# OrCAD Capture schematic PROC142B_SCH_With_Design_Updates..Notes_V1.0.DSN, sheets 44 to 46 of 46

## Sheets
44 44. OSCILLATOR: size C; title: SOC RESETs AND IOs, AND EXTERNAL LVCMOS CLOCK (OSCILLATOR)
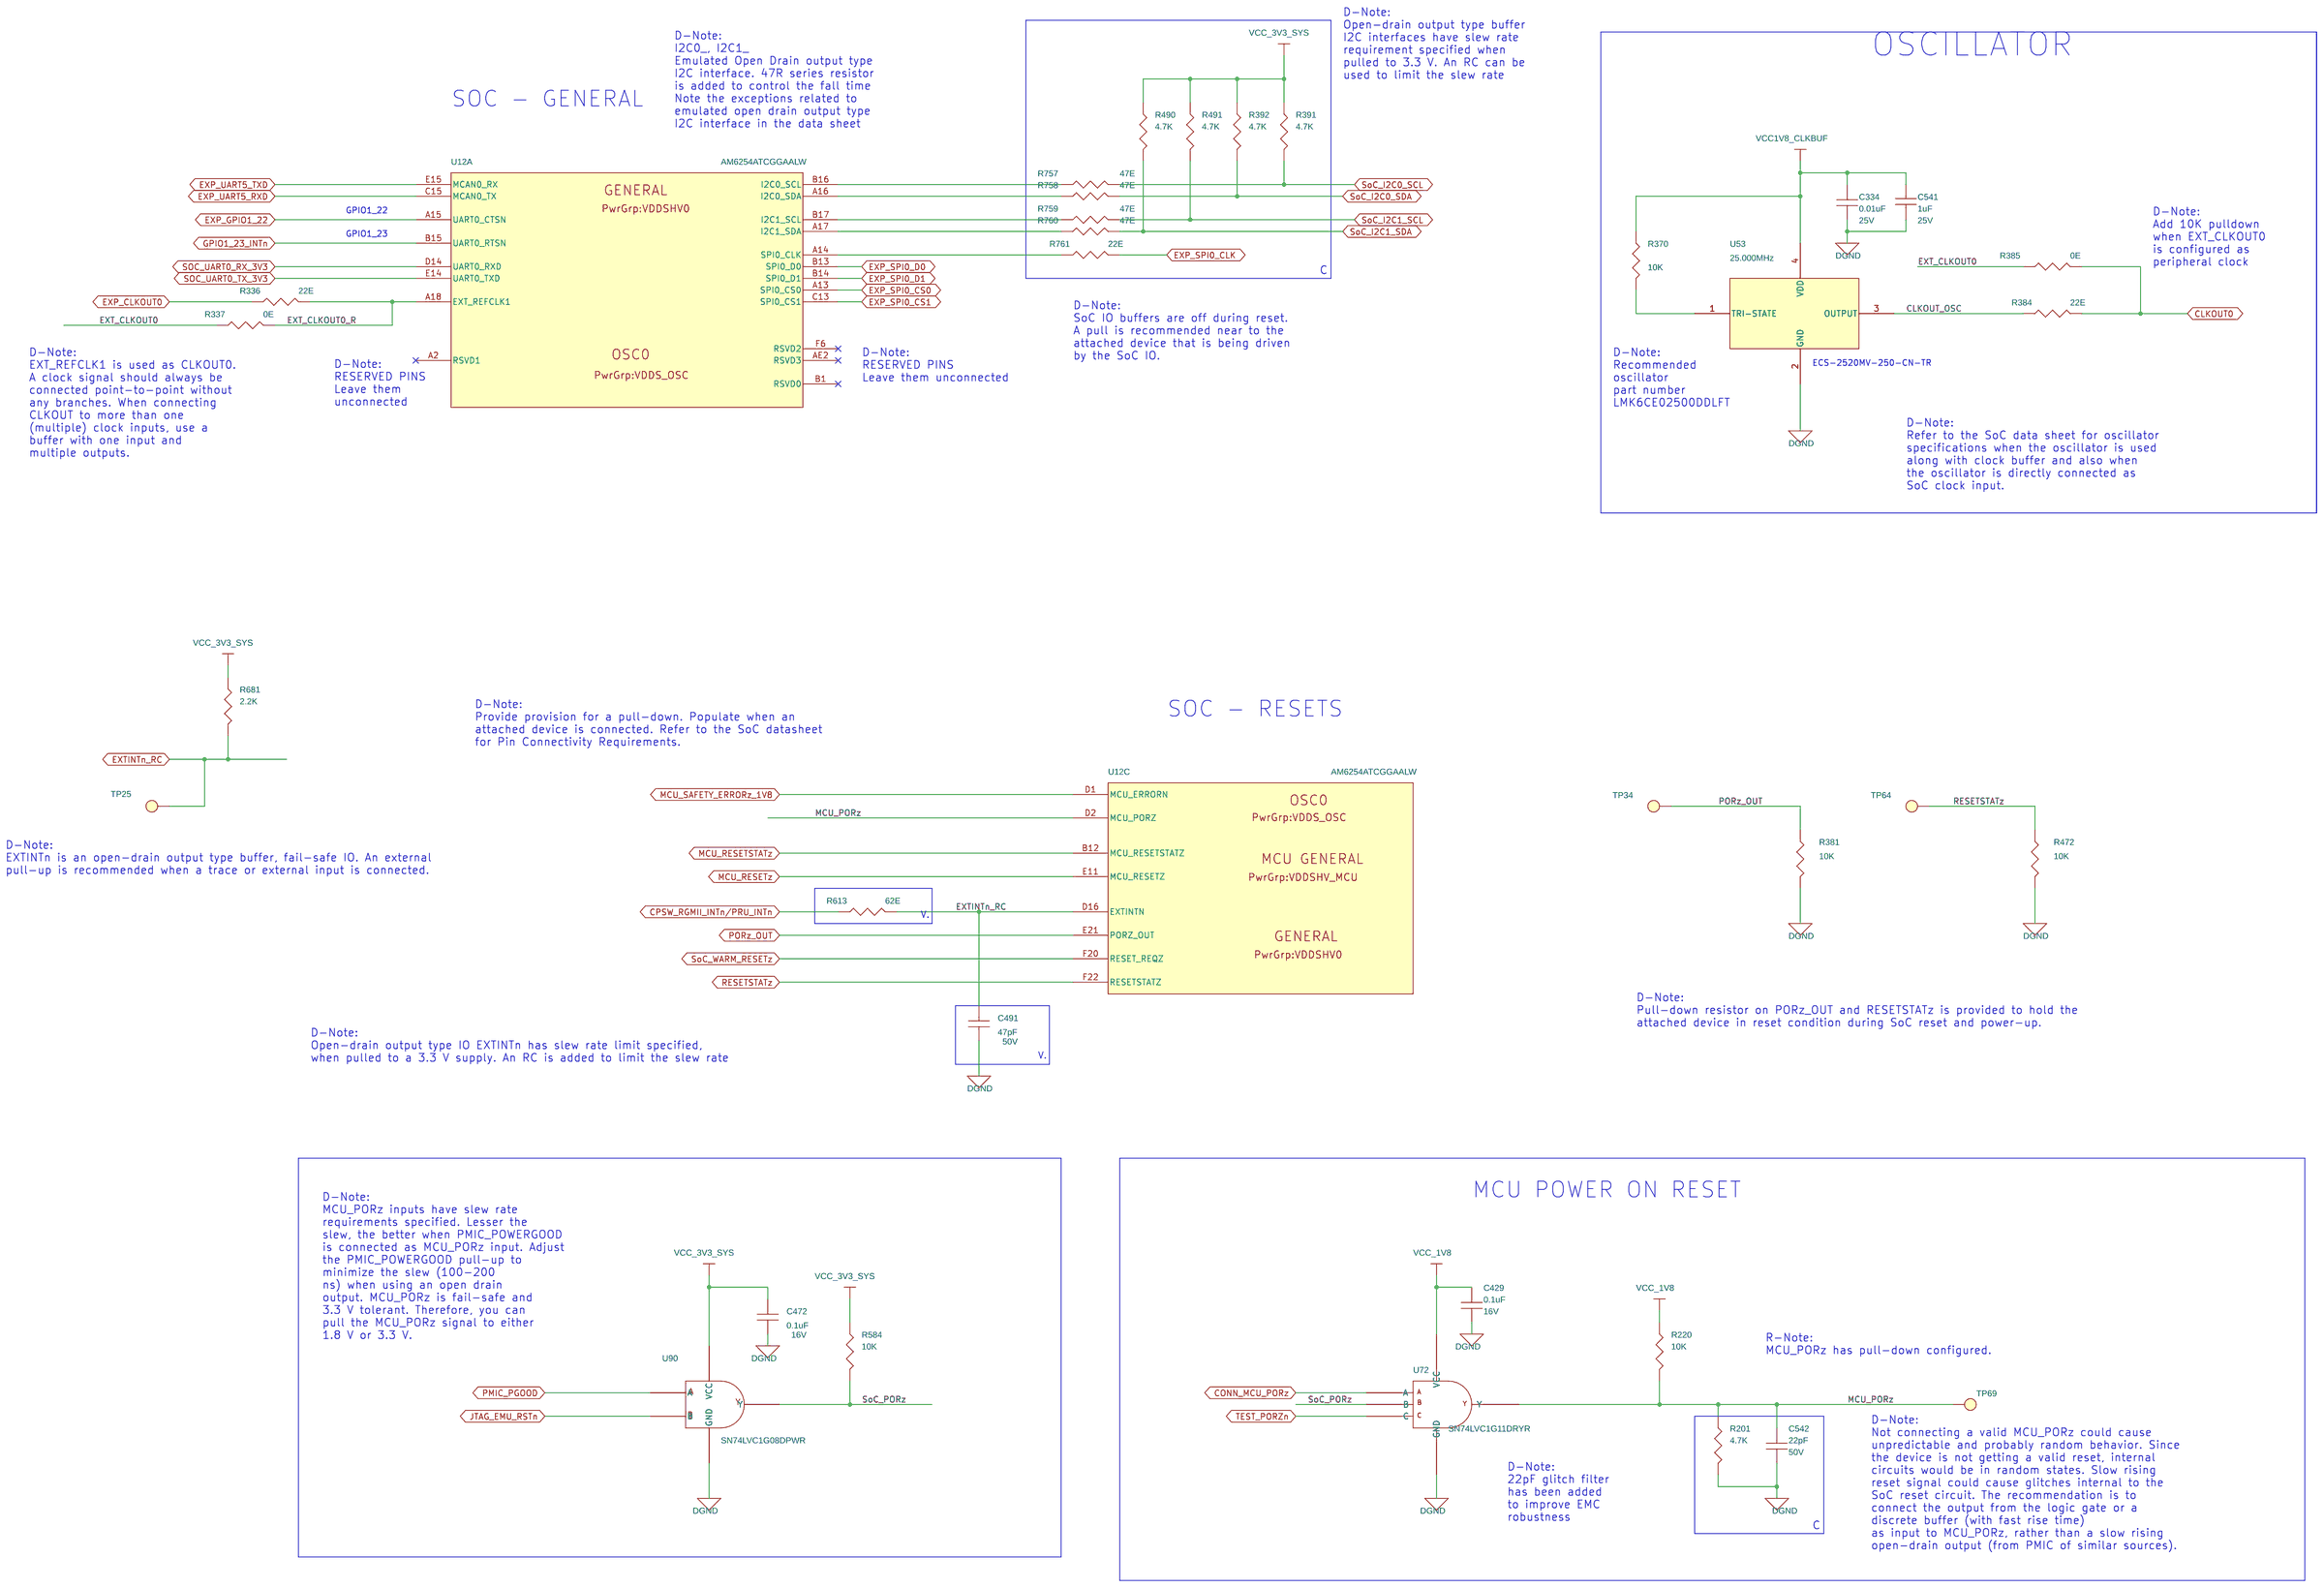
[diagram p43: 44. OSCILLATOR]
45 45. RESET: size C; title: SOC PUSH BUTTON RESET INPUTS, DEBOUNCE LOGIC FOR RC RESET
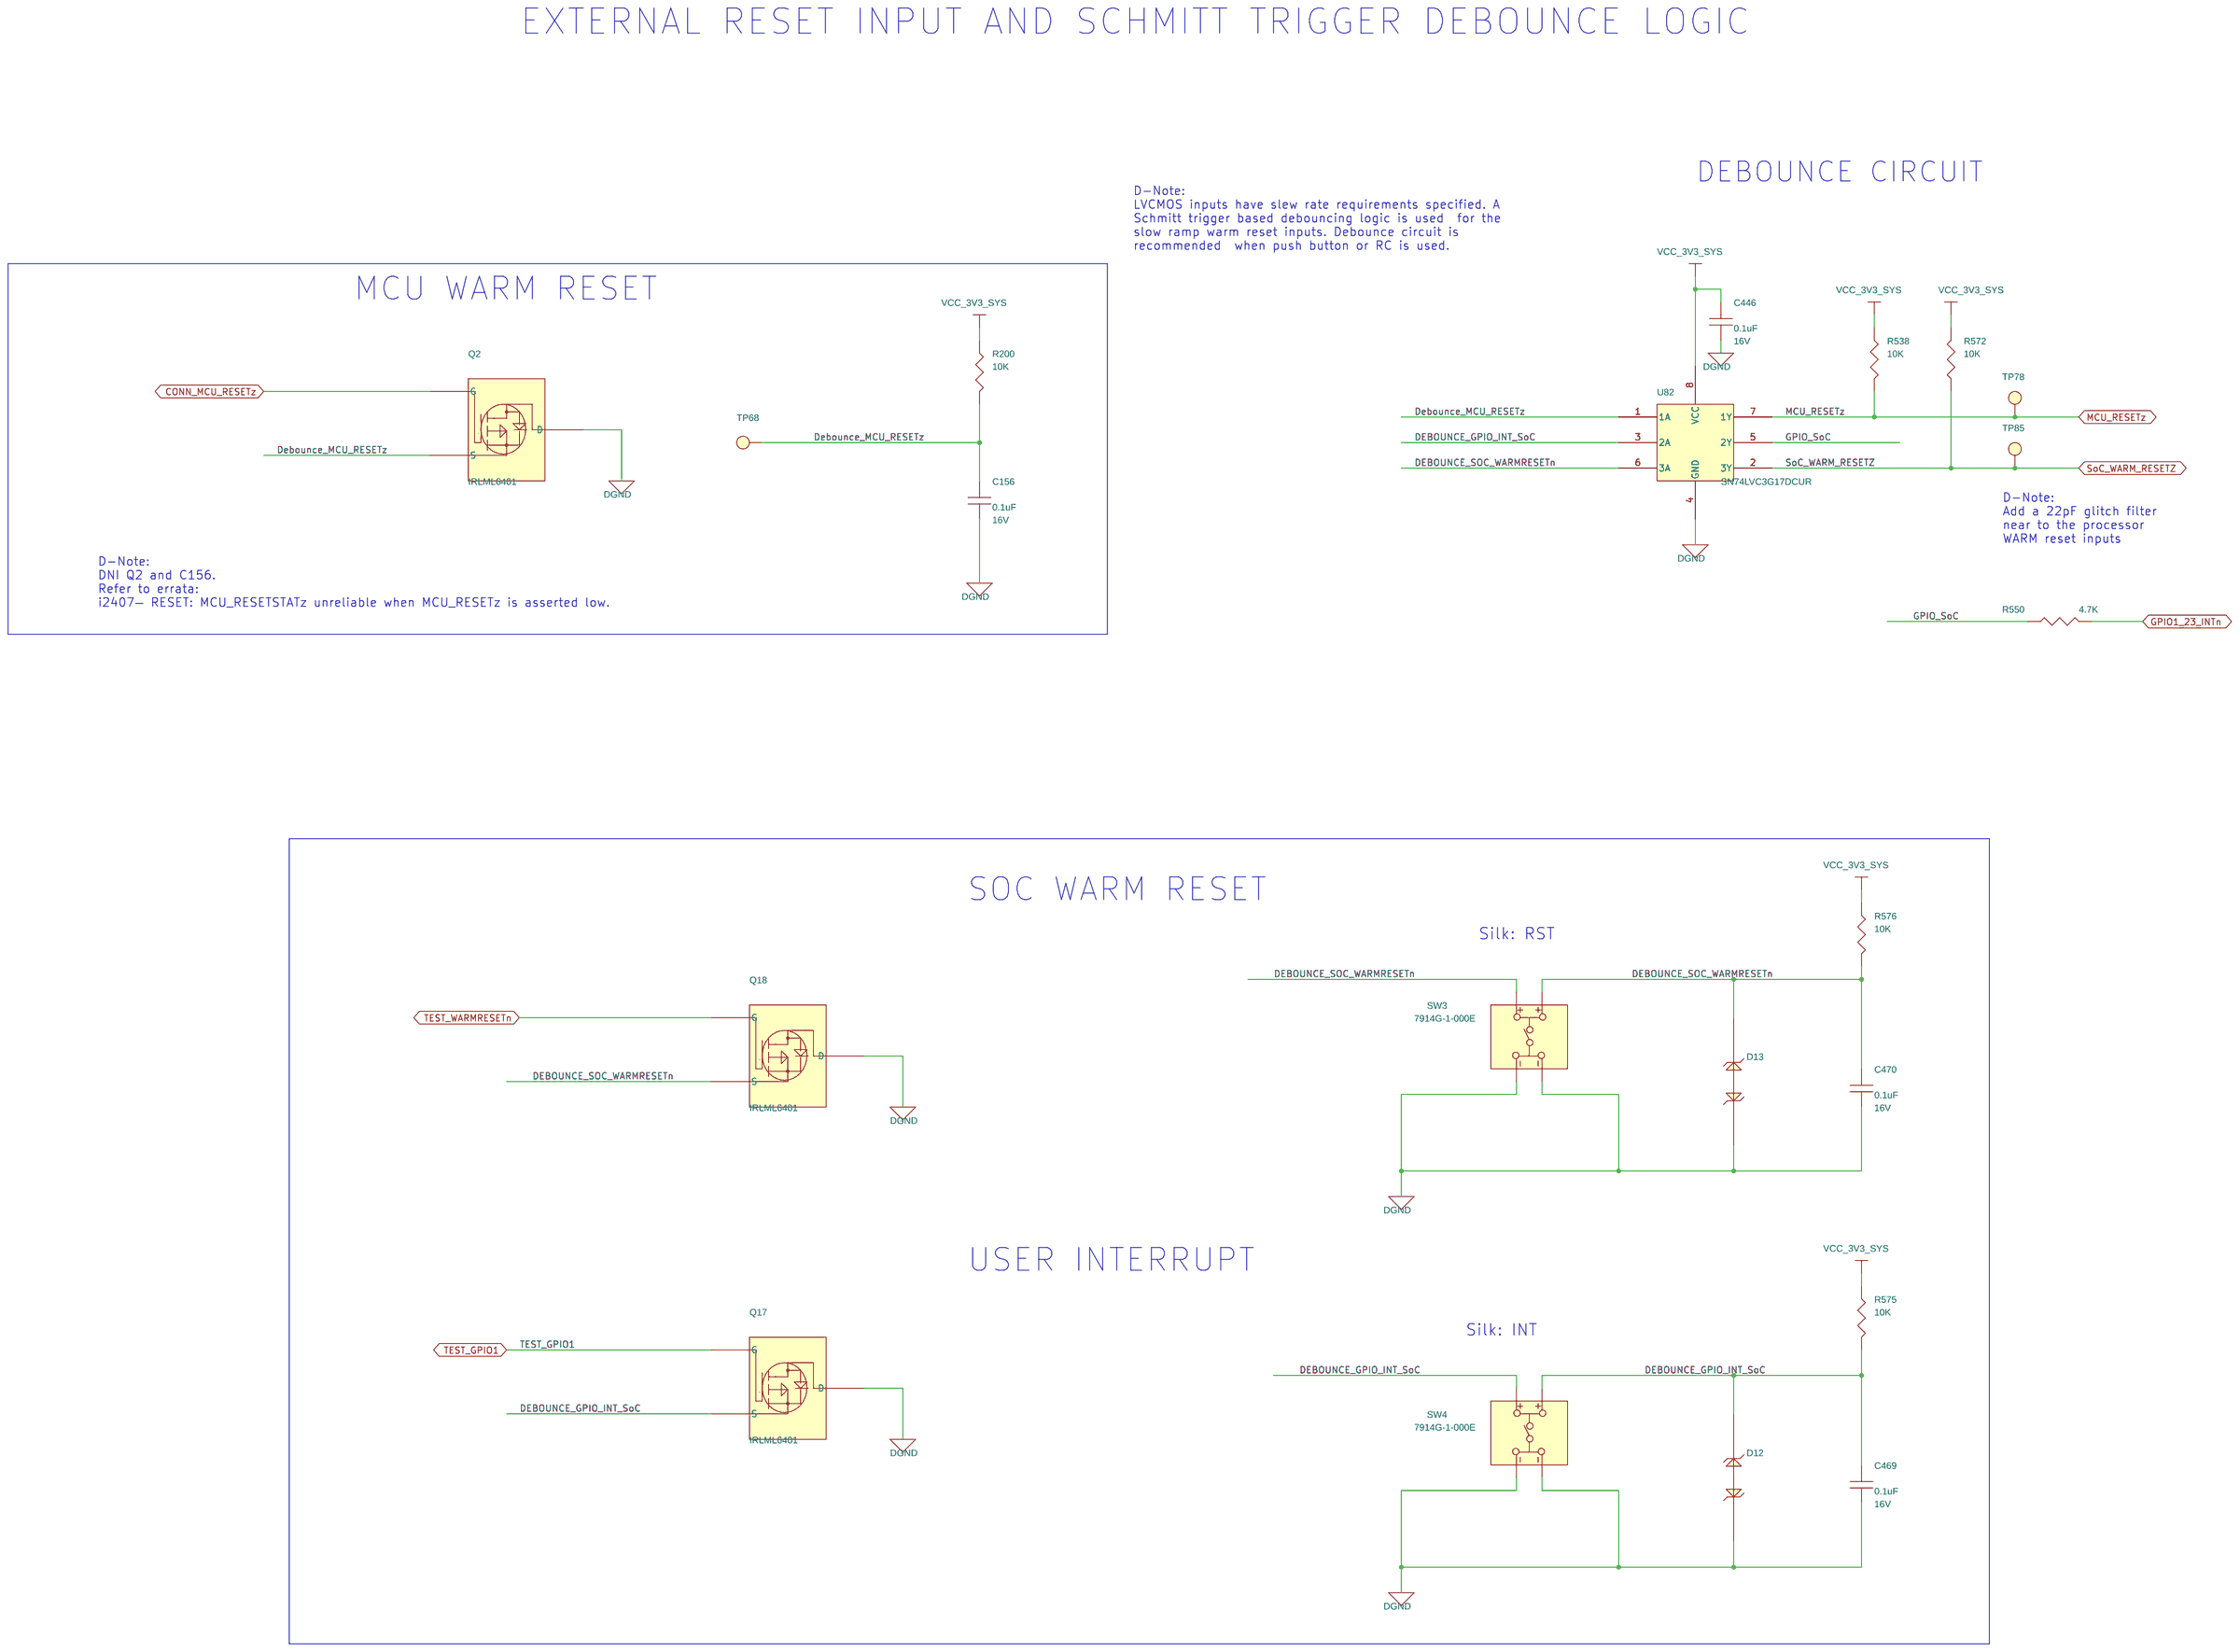
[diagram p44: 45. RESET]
46 46. ACCESSORIES: title: ASSEMBLY NOTES AND MOUNTING HARDWARE
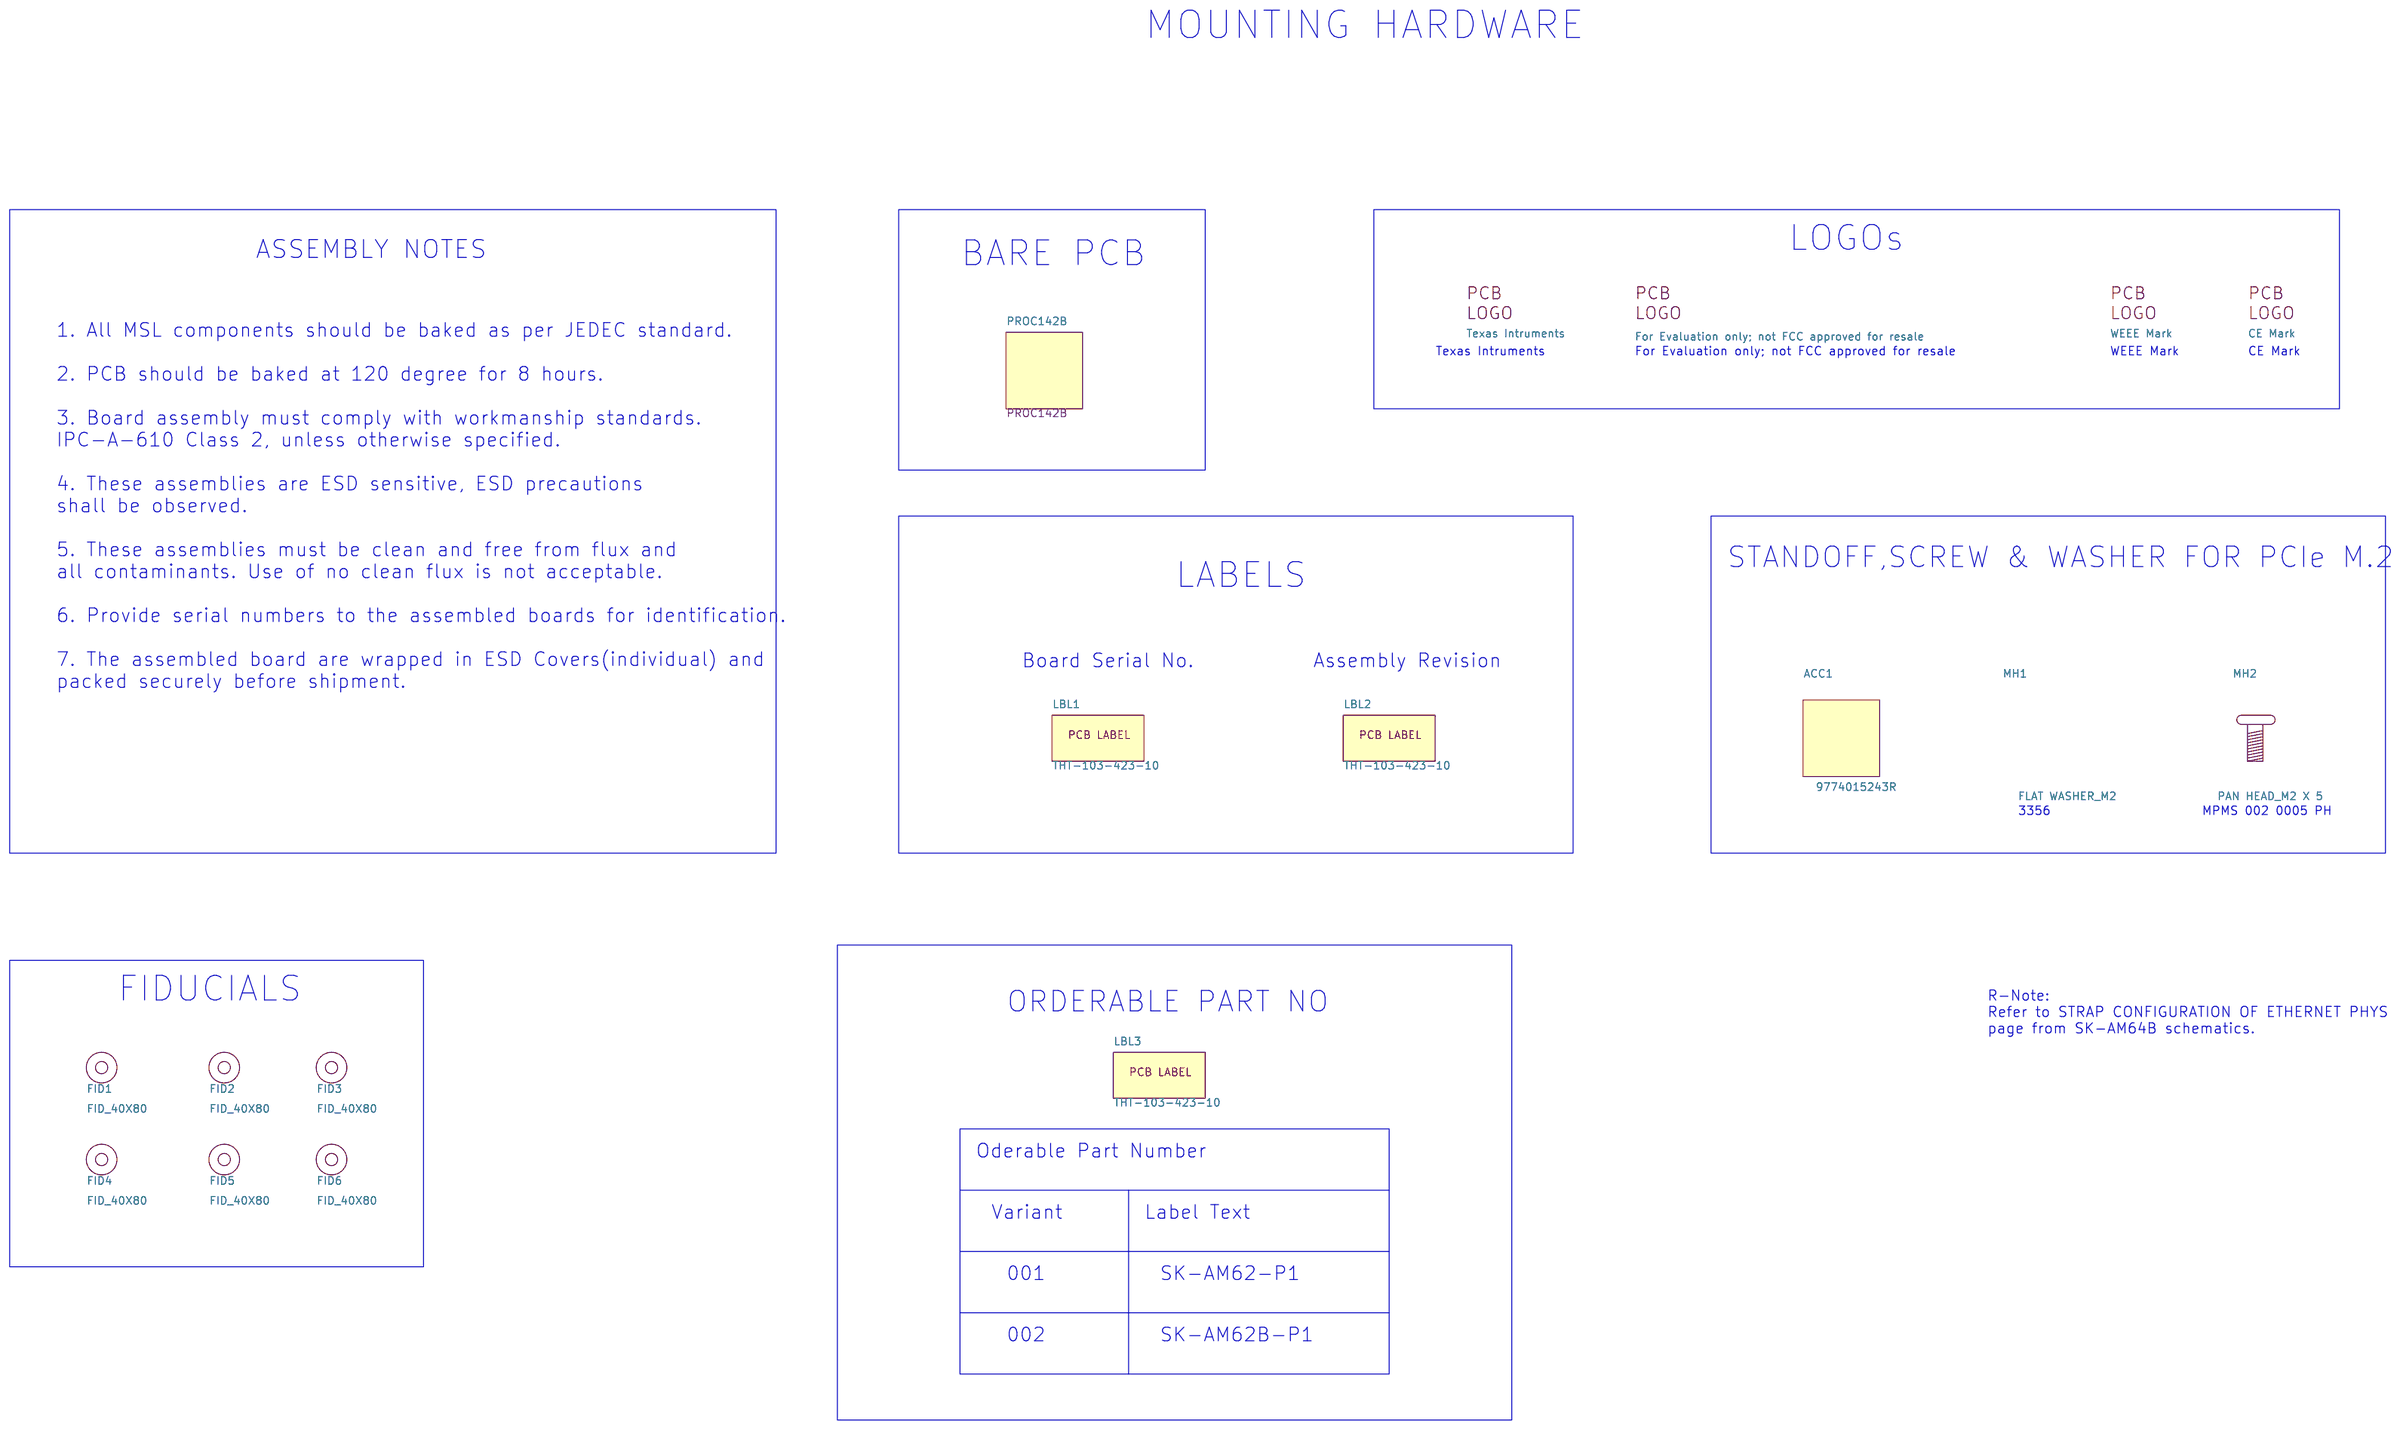
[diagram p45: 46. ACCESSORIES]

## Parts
sheet 43. HDMI INTERFACE
U12  AM6254ATCGGAALW  [BGA425_19-68_510X510_0-7]  (sections A,B,C,D,E,F,G,H,I,J,K,L,M,N,O,P,Q,R)
sheet 44. OSCILLATOR
C334  0.01uF  [CAP0201_0-5]
C429  0.1uF  [CAP0201_0-5]
C472  0.1uF  [CAP0201_0-5]
C491  47pF  [CAP0201_0-5]
C541  1uF  [CAP0402_0-75]
C542  22pF  [CAP0402_0-75]
R201  4.7K  [RES0201_0-5]
R220  10K  [RES0201_0-5]
R336  22E  [RES0402_0-5]
R337  0E  [RES0402_0-5]
R370  10K  [RES0402_0-5]
R381  10K  [RES0201_0-5]
R384  22E  [RES0402_0-5]
R385  0E  [RES0201_0-5]
R391  4.7K  [RES0201_0-5]
R392  4.7K  [RES0201_0-5]
R472  10K  [RES0201_0-5]
R490  4.7K  [RES0201_0-5]
R491  4.7K  [RES0201_0-5]
R584  10K  [RES0201_0-5]
R613  62E  [RES0201_0-5]
R681  2.2K  [RES0201_0-5]
R757  47E  [RES0201_0-5]
R758  47E  [RES0201_0-5]
R759  47E  [RES0201_0-5]
R760  47E  [RES0201_0-5]
R761  22E  [RES0201_0-5]
TP25  TP20_SMD  [TP20_SMD]
TP34  TP20_SMD  [TP20_SMD]
TP64  TP20_SMD  [TP20_SMD]
TP69  TP20_SMD  [TP20_SMD]
U53  25.000MHz  [OSC4_ECS-2520MV_100X80_SMD_0-9]
U72  SN74LVC1G11DRYR  [SON6_SN74LVC2G17_40X60_0-6]
U90  SN74LVC1G08DPWR  [X2SON5_TLV7021_30X30_0-4]
sheet 45. RESET
C156  0.1uF  [CAP0201_0-5]
C446  0.1uF  [CAP0201_0-5]
C469  0.1uF  [CAP0201_0-5]
C470  0.1uF  [CAP0201_0-5]
D12  TPD1E10B06DPYR  [DIO_DFN0402_0-5]
D13  TPD1E10B06DPYR  [DIO_DFN0402_0-5]
Q2  IRLML6401  [TO_SOT23-123]
Q17  IRLML6401  [TO_SOT23-123]
Q18  IRLML6401  [TO_SOT23-123]
R200  10K  [RES0201_0-5]
R538  10K  [RES0201_0-5]
R550  4.7K  [RES0201_0-5]
R572  10K  [RES0201_0-5]
R575  10K  [RES0201_0-5]
R576  10K  [RES0201_0-5]
SW3  7914G-1-000E  [SW4_100X216_200X200_SMD_4-2]
SW4  7914G-1-000E  [SW4_100X216_200X200_SMD_4-2]
TP68  TP20_SMD  [TP20_SMD]
TP78  TP20_SMD  [TP20_SMD]
TP85  TP20_SMD  [TP20_SMD]
U82  SN74LVC3G17DCUR  [VSSOP8_19-68_85X95_0-9]
sheet 46. ACCESSORIES
ACC1  9774015243R  [NA]
FID1  FID_40X80  [FID_40X80]
FID2  FID_40X80  [FID_40X80]
FID3  FID_40X80  [FID_40X80]
FID4  FID_40X80  [FID_40X80]
FID5  FID_40X80  [FID_40X80]
FID6  FID_40X80  [FID_40X80]
LBL1  THT-103-423-10  [NA]
LBL2  THT-103-423-10  [NA]
LBL3  THT-103-423-10  [NA]
LOGO1  Texas Intruments  [TI_Stacked_Overlay_Small]
LOGO2  For Evaluation only; not FCC approved for resale  [FCC_disclaimer]
LOGO3  WEEE Mark  [TI_Stacked_Overlay_Small]
LOGO4  CE Mark  [TI_Stacked_Overlay_Small]
MH1  FLAT WASHER_M2  [NA]
MH2  PAN HEAD_M2 X 5  [NA]
PCB1  PROC142B

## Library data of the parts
U12 = AM62-EVM_BGA425: IC AM62 SoC MICROPROCESSOR BGA425; Chkd/date: ALVY/110621; Crtd /date: MANIRAJA/110621; Custom_Duty: 15%; Customs_HS_Code: 85423100; Distributor_name: NA; Distributor_part_number: NA; Footprint Path: Y:\MIS_DATABASE\Library\ALTIUM_TOOL\PCB_FOOTPRINTS\Altium_Footprint_Lib.PcbLib; Height: 0.65MM; Library Path: Y:\MIS_DATABASE\Library\ALTIUM_TOOL\SCHEMATICS_PARTS\MS_MICROPROCESSOR_Library.schlib; Mfr_name: TEXAS INSTRUMENTS; Mistral Part No: 141221060001; Package: BGA425; Part_type: ICS\DIGITAL\MICROPROCESSOR; Project: AM62_EVM_BRD; RoHS: NA; Temperature: NA; Tolerance: NA; Voltage: NA; Wattage: NA; Weight: NA; Datasheet: Y:\MIS_DATABASE\DATASHEETS\ICS\DIGITAL\MICROCONTROLLER\AM62-SoC_SVB.PDF
C334 = CAP: CAP CERAMIC 0.01uF 25V 10% X5R 0201; Chkd/date: MANIRAJA/230118; Crtd /date: MANIRAJA/230118; Custom_Duty: 15%; Customs_HS_Code: 85322990; Distributor_name: DIGIKEY; Distributor_part_number: GRM033R61E103KA12J-ND; Footprint Path: Y:\MIS_DATABASE\Library\ALTIUM_TOOL\PCB_FOOTPRINTS\Altium_Footprint_Lib.PcbLib; Height: 0.33MM; Library Path: Y:\MIS_DATABASE\Library\ALTIUM_TOOL\SCHEMATICS_PARTS\MS_DISCRETE_Library.schlib; Mfr_name: MURATA; Mfr_part_number: GRM033R61E103KA12J; Mistral Part No: 120018010007-R; Package: 0201; Part_type: CAPACITORS\CERAMIC; Project: TI_MAXIE_CPB; RoHS: RoHS; Temperature: -55°C+85°C; Tolerance: 10%; Voltage: 25V; Wattage: NA; Weight: 0.33mg; Datasheet: Y:\MIS_DATABASE\DATASHEETS\CAPACITORS\GRM033R61E103KA12.PDF
C156 C429 C446 C469 C470 C472 = CAP: CAP CERAMIC 0.1uF 16V 10% X5R 0201; Alt_Mfr_name: YAGEO AMERICA; Alt_Mfr_part_number: CC0402KRX5R8BB104; Chkd/date: MANIRAJA/230118; Crtd /date: MANIRAJA/230118; Custom_Duty: 15%; Customs_HS_Code: 85322990; Distributor_name: DIGIKEY; Distributor_part_number: 490-14305-1-ND; Footprint Path: Y:\MIS_DATABASE\Library\ALTIUM_TOOL\PCB_FOOTPRINTS\Altium_Footprint_Lib.PcbLib; Height: 0.33MM; Library Path: Y:\MIS_DATABASE\Library\ALTIUM_TOOL\SCHEMATICS_PARTS\MS_DISCRETE_Library.schlib; Mfr_name: MURATA; Mfr_part_number: GRM033R61C104KE14D; Mistral Part No: 120009030072-R; Package: 0201; Part_type: CAPACITORS\CERAMIC; Project: TI_MAXIE_CPB; RoHS: RoHS; Temperature: -55°C+85°C; Tolerance: 10%; Voltage: 16V; Wattage: NA; Weight: 0.33mg; Datasheet: Y:\MIS_DATABASE\DATASHEETS\CAPACITORS\GRM033R61C104KE14.PDF
C491 = CAP: CAP CERAMIC 47pF 50V 5% C0G(NP0) AUTO 0201; Chkd/date: MANIRAJA/311221; Crtd /date: ALVY/301221; Custom_Duty: 15%; Customs_HS_Code: 85322990; Distributor_name: MOUSER; Distributor_part_number: 81-GRT0335C1H470JA2D; Footprint Path: Y:\MIS_DATABASE\Library\ALTIUM_TOOL\PCB_FOOTPRINTS\Altium_Footprint_Lib.PcbLib; Height: 0.33MM; Library Path: Y:\MIS_DATABASE\Library\ALTIUM_TOOL\SCHEMATICS_PARTS\MS_DISCRETE_Library.schlib; Mfr_name: MURATA; Mfr_part_number: GRT0335C1H470JA02D; Mistral Part No: 120021120018-R; Package: 0201; Part_type: CAPACITORS\CERAMIC; Project: AM62Q_SKEVM_BRD; RoHS: RoHS; Temperature: -55°C+125°C; Tolerance: 5%; Voltage: 50V; Wattage: NA; Weight: 0.33mg; Datasheet: Y:\MIS_DATABASE\DATASHEETS\CAPACITORS\GRT0335C1H470JA02.PDF
C541 = CAP: CAP CERAMIC 1uF 25V 10% X6S 0402; Chkd/date: MANIRAJA/140518; Crtd /date: ALVY/140518; Custom_Duty: 15%; Customs_HS_Code: 85322990; Distributor_name: DIGIKEY; Distributor_part_number: 490-10014-1-ND; Footprint Path: Y:\MIS_DATABASE\Library\ALTIUM_TOOL\PCB_FOOTPRINTS\Altium_Footprint_Lib.PcbLib; Height: 0.60MM; Library Path: Y:\MIS_DATABASE\Library\ALTIUM_TOOL\SCHEMATICS_PARTS\MS_DISCRETE_Library.schlib; Mfr_name: MURATA; Mfr_part_number: GRM155C81E105KE11D; Mistral Part No: 120018050004-R; Package: 0402; Part_type: CAPACITORS\CERAMIC; Project: TI_SVB_MAXWELL_DUT; RoHS: RoHS; Temperature: -55°C+105°C; Tolerance: 10%; Voltage: 25V; Wattage: NA; Weight: 6mg; Datasheet: Y:\MIS_DATABASE\DATASHEETS\CAPACITORS\GRM155C81E105KE11X.PDF
C542 = CAP: CAP CERAMIC 22pF 50V 5% C0G(NP0) 0402; Chkd/date: MANIRAJA/290421; Crtd /date: ALVY/290421; Custom_Duty: 15%; Customs_HS_Code: 85322990; Distributor_name: DIGIKEY; Distributor_part_number: 490-5868-1-ND; Footprint Path: Y:\MIS_DATABASE\Library\ALTIUM_TOOL\PCB_FOOTPRINTS\Altium_Footprint_Lib.PcbLib; Height: 0.55MM; Library Path: Y:\MIS_DATABASE\Library\ALTIUM_TOOL\SCHEMATICS_PARTS\MS_DISCRETE_Library.schlib; Mfr_name: MURATA; Mfr_part_number: GRM1555C1H220JA01D; Mistral Part No: 120014100023-R; Package: 0402; Part_type: CAPACITORS\CERAMIC; Project: SRMS-SAR_BRD; RoHS: RoHS; Temperature: -55°C+125°C; Tolerance: 5%; Voltage: 50V; Wattage: NA; Weight: 1.6mg; Datasheet: Y:\MIS_DATABASE\DATASHEETS\CAPACITORS\GRM1555C1H220JA01.PDF
R201 R391 R392 R490 R491 = RESISTOR: RES 4.7K 1/20W 5% 0201; Chkd/date: MANIRAJA/200921; Crtd /date: ALVY/200921; Custom_Duty: 15%; Customs_HS_Code: 85332119; Distributor_name: DIGIKEY; Distributor_part_number: 311-4.7KNCT-ND; Footprint Path: Y:\MIS_DATABASE\Library\ALTIUM_TOOL\PCB_FOOTPRINTS\Altium_Footprint_Lib.PcbLib; Height: 0.26MM; Library Path: Y:\MIS_DATABASE\Library\ALTIUM_TOOL\SCHEMATICS_PARTS\MS_DISCRETE_Library.schlib; Mfr_name: YAGEO AMERICA; Mfr_part_number: RC0201JR-074K7L; Mistral Part No: 110021090007-R; Package: 0201; Part_type: RESISTORS\FIXED; Project: TI_AM62x SKEVM_BRD; RoHS: RoHS; Temperature: -55°C+125°C; Tolerance: 5%; Voltage: NA; Wattage: 1/20W; Weight: 0.17mg; Datasheet: Y:\MIS_DATABASE\DATASHEETS\RESISTORS\RCXXXXL-SER_MAR18.PDF
R200 R220 R381 R472 R538 R572 R575 R576 R584 = RESISTOR: RES 10K 1/20W 5% 0201; Chkd/date: MANIRAJA/050517; Crtd /date: MANIRAJA/050517; Custom_Duty: 15%; Customs_HS_Code: 85332119; Distributor_name: DIGIKEY; Distributor_part_number: 311-10KNCT-ND; Footprint Path: Y:\MIS_DATABASE\Library\ALTIUM_TOOL\PCB_FOOTPRINTS\Altium_Footprint_Lib.PcbLib; Height: 0.26MM; Library Path: Y:\MIS_DATABASE\Library\ALTIUM_TOOL\SCHEMATICS_PARTS\MS_DISCRETE_Library.schlib; Mfr_name: YAGEO AMERICA; Mfr_part_number: RC0201JR-0710KL; Mistral Part No: 110010070051-R; Package: 0201; Part_type: RESISTORS\FIXED; Project: GOLDEN-I LITE; RoHS: RoHS; Temperature: -55°C+125°C; Tolerance: 5%; Voltage: NA; Wattage: 1/20W; Weight: 0.17mg; Datasheet: Y:\MIS_DATABASE\DATASHEETS\RESISTORS\RCXXXXL-SER_MAR18.PDF
R336 R384 = RESISTOR: RES 22E 1/16W 5% 0402; Chkd/date: ALVY/210122; Crtd /date: TAMILARASU/210122; Custom_Duty: 15%; Customs_HS_Code: 85332119; Distributor_name: DIGIKEY; Distributor_part_number: 311-22JRCT-ND; Footprint Path: Y:\MIS_DATABASE\Library\ALTIUM_TOOL\PCB_FOOTPRINTS\Altium_Footprint_Lib.PcbLib; Height: 0.40MM; Library Path: Y:\MIS_DATABASE\Library\ALTIUM_TOOL\SCHEMATICS_PARTS\MS_DISCRETE_Library.schlib; Manufacturer: YAGEO; Mfr_name: YAGEO AMERICA; Mfr_part_number: RC0402JR-0722RL; Mistral Part No: 110022010018-R; Package: 0402; Part_type: RESISTORS\FIXED; Project: DLRL DIGITAL RECEIVER_BRD; RoHS: RoHS; Temperature: -55°C+155°C; Tolerance: 5%; Voltage: NA; Wattage: 1/16W; Weight: 0.65mg; Datasheet: Y:\MIS_DATABASE\DATASHEETS\RESISTORS\RCXXXXP-SER_SEP18.PDF
R337 = RESISTOR: RES 0E 1/16W JUMPER 0402; Chkd/date: VASANTHA/201216; Crtd /date: MUDDU/190810; Custom_Duty: 15%; Customs_HS_Code: 85332119; Distributor_name: DIGIKEY; Distributor_part_number: 541-0.0JCT-ND; Footprint Path: Y:\MIS_DATABASE\Library\ALTIUM_TOOL\PCB_FOOTPRINTS\Altium_Footprint_Lib.PcbLib; Height: 0.40MM; Library Path: Y:\MIS_DATABASE\Library\ALTIUM_TOOL\SCHEMATICS_PARTS\MS_DISCRETE_Library.schlib; Mfr_name: VISHAY; Mfr_part_number: CRCW04020000Z0ED; Mistral Part No: 110010080019-R; Package: 0402; Part_type: RESISTORS\FIXED; Project: PB_BUGBASE; RoHS: RoHS; Temperature: -55°C+155°C; Tolerance: NA; Voltage: NA; Wattage: 1/16W; Weight: 0.65mg; Datasheet: Y:\MIS_DATABASE\DATASHEETS\RESISTORS\CRCW0603.PDF
R370 = RESISTOR: RES 10K 1/16W 5% 0402; Chkd/date: MANIRAJA/120219; Crtd /date: MANIRAJA/120219; Custom_Duty: 15%; Customs_HS_Code: 85332119; Distributor_name: DIGIKEY; Distributor_part_number: 541-10KJCT-ND; Footprint Path: Y:\MIS_DATABASE\Library\ALTIUM_TOOL\PCB_FOOTPRINTS\Altium_Footprint_Lib.PcbLib; Height: 0.40MM; Library Path: Y:\MIS_DATABASE\Library\ALTIUM_TOOL\SCHEMATICS_PARTS\MS_DISCRETE_Library.schlib; Mfr_name: VISHAY; Mfr_part_number: CRCW040210K0JNED; Mistral Part No: 110011060021-R; Package: 0402; Part_type: RESISTORS\FIXED; Project: NEXTNAV_ORBIT_MODULE; RoHS: RoHS; Temperature: -55°C+155°C; Tolerance: 5%; Voltage: NA; Wattage: 1/16W; Weight: 0.65mg; Datasheet: Y:\MIS_DATABASE\DATASHEETS\RESISTORS\CRCW0603.PDF
R385 = RESISTOR: RES 0E 1/20W 5% 0201; Chkd/date: NAVEED/301214; Crtd /date: MUDDU/120710; Custom_Duty: 15%; Customs_HS_Code: 85332119; Distributor_name: DIGIKEY; Distributor_part_number: 311-0.0NCT-ND; Footprint Path: Y:\MIS_DATABASE\Library\ALTIUM_TOOL\PCB_FOOTPRINTS\Altium_Footprint_Lib.PcbLib; Height: 0.26MM; Library Path: Y:\MIS_DATABASE\Library\ALTIUM_TOOL\SCHEMATICS_PARTS\MS_DISCRETE_Library.schlib; Mfr_name: YAGEO AMERICA; Mfr_part_number: RC0201JR-070RL; Mistral Part No: 110010070067-R; Package: 0201; Part_type: RESISTORS\FIXED; Project: PB_BUGBASE; RoHS: RoHS; Temperature: -55°C+125°C; Tolerance: 5%; Voltage: NA; Wattage: 1/20W; Weight: 0.17mg; Datasheet: Y:\MIS_DATABASE\DATASHEETS\RESISTORS\RCXXXXL-SER_MAR18.PDF
R613 = RESISTOR: RES 62E 1/20W 1% 0201; Chkd/date: PRADEEP/230326; Crtd /date: SHANKARI/230326; Custom_Duty: 15%; Customs_HS_Code: 85332119; Distributor_name: DIGIKEY; Distributor_part_number: P123108CT-ND; Footprint Path: Y:\MIS_DATABASE\Library\ALTIUM_TOOL\PCB_FOOTPRINTS\Altium_Footprint_Lib.PcbLib; Height: 0.26MM; Library Path: Y:\MIS_DATABASE\Library\ALTIUM_TOOL\SCHEMATICS_PARTS\MS_DISCRETE_Library.schlib; Mfr_name: PANASONIC; Mfr_part_number: ERJ-1GNF62R0C; Mistral Part No: 110026030006-R; Package: 0201; Part_type: RESISTORS\FIXED; Project: AM62X_FULTON_REV B; RoHS: RoHS; Temperature: -55°C+125°C; Tolerance: 0.01; Voltage: NA; Wattage: 1/20W; Weight: NA; Datasheet: Y:\MIS_DATABASE\DATASHEETS\RESISTORS\ERJ-1GNF62R0C.PDF
R681 = RESISTOR: RES 2.2K 1/20W 5% 0201; Chkd/date: VASANTHA/010117; Crtd /date: MAZHAR/010605; Custom_Duty: 15%; Customs_HS_Code: 85332119; Distributor_name: DIGIKEY; Distributor_part_number: P2.2KAGCT-ND; Footprint Path: Y:\MIS_DATABASE\Library\ALTIUM_TOOL\PCB_FOOTPRINTS\Altium_Footprint_Lib.PcbLib; Height: 0.26MM; Library Path: Y:\MIS_DATABASE\Library\ALTIUM_TOOL\SCHEMATICS_PARTS\MS_DISCRETE_Library.schlib; Mfr_name: PANASONIC-ECG; Mfr_part_number: ERJ-1GEJ222C; Mistral Part No: 110009030427-R; Package: 0201; Part_type: RESISTORS\FIXED; Project: G4SLIM; RoHS: RoHS; Temperature: -55°C+125°C; Tolerance: 5%; Voltage: NA; Wattage: 1/20W; Weight: 0.15mg; Datasheet: Y:\MIS_DATABASE\DATASHEETS\RESISTORS\PAN-ERJXGE-FEB06.PDF
R757-R760 = RESISTOR: RES 47E 1/20W 5% 0201; Chkd/date: MAZHAR/140709; Crtd /date: MAZHAR/260907; Custom_Duty: 15%; Customs_HS_Code: 85332119; Distributor_name: DIGIKEY; Distributor_part_number: P47AGCT-ND; Footprint Path: Y:\MIS_DATABASE\Library\ALTIUM_TOOL\PCB_FOOTPRINTS\Altium_Footprint_Lib.PcbLib; Height: 0.26MM; Library Path: Y:\MIS_DATABASE\Library\ALTIUM_TOOL\SCHEMATICS_PARTS\MS_DISCRETE_Library.schlib; Mfr_name: PANASONIC-ECG; Mfr_part_number: ERJ-1GEJ470C; Mistral Part No: 110009030875-R; Package: 0201; Part_type: RESISTORS\FIXED; Project: SMART VIEW_NVR; RoHS: RoHS; Temperature: -55°C+125°C; Tolerance: 5%; Voltage: NA; Wattage: 1/20W; Weight: 0.15mg; Datasheet: Y:\MIS_DATABASE\DATASHEETS\RESISTORS\PAN-ERJXGE-FEB06.PDF
R761 = RESISTOR: RES 22E 1/20W 5% 0201; Chkd/date: PRADEEP/220424; Crtd /date: SHANKARI/220424; Custom_Duty: 15%; Customs_HS_Code: 85332119; Distributor_name: DIGIKEY; Distributor_part_number: 311-22NCT-ND; Footprint Path: Y:\MIS_DATABASE\Library\ALTIUM_TOOL\PCB_FOOTPRINTS\Altium_Footprint_Lib.PcbLib; Height: 0.26MM; Library Path: Y:\MIS_DATABASE\Library\ALTIUM_TOOL\SCHEMATICS_PARTS\MS_DISCRETE_Library.schlib; Manufacturer: YAGEO; Mfr_name: YAGEO; Mfr_part_number: RC0201JR-0722RL; Mistral Part No: 110024040012-R; Package: 0201; Part_type: RESISTORS\FIXED; Project: J7AEN_SKEVM; RoHS: RoHS; Temperature: -55°C+125°C; Tolerance: 5%; Voltage: NA; Wattage: 1/20W; Weight: NA; Datasheet: Y:\MIS_DATABASE\DATASHEETS\RESISTORS\RC0201JR-0722RL.PDF
TP25 TP34 TP64 TP68 TP69 TP78 TP85 = TESTPOINT: TESTPOINT CIR 20 SMD; Chkd/date: SHREESHAIL/171006; Crtd /date: MAZHAR/171006; Custom_Duty: NA; Customs_HS_Code: NA; Distributor_name: NA; Distributor_part_number: NA; Footprint Path: Y:\MIS_DATABASE\Library\ALTIUM_TOOL\PCB_FOOTPRINTS\Altium_Footprint_Lib.PcbLib; Height: NA; Library Path: Y:\MIS_DATABASE\Library\ALTIUM_TOOL\SCHEMATICS_PARTS\MS_DISCRETE_Library.schlib; MECHANICAL 3D STEP FILE: NA; Mfr_name: LOCAL; Mistral Part No: NA; Package: SMD; Project: BT MODULE_CSRBC04; RoHS: NA; Temperature: NA; Tolerance: NA; Voltage: NA; Wattage: NA; Weight: NA; Datasheet: NA
U53 = OSC4_ASFL3: OSC 25.000MHz CMOS SMD; Chkd/date: MANIRAJA/181120; Crtd /date: ALVY/181120; Custom_Duty: 24%; Customs_HS_Code: 85437099; Distributor_name: DIGIKEY; Distributor_part_number: XC2752CT-ND; Footprint Path: Y:\MIS_DATABASE\Library\ALTIUM_TOOL\PCB_FOOTPRINTS\Altium_Footprint_Lib.PcbLib; Height: 0.90MM; Library Path: Y:\MIS_DATABASE\Library\ALTIUM_TOOL\SCHEMATICS_PARTS\MS_DISCRETE_Library.schlib; Mfr_name: ECS INC; Mfr_part_number: ECS-2520MV-250-CN-TR; Mistral Part No: 130020110041-R; Package: SMD; Part_type: OSCILLATORS; Project: AM64X_SKEVM; RoHS: RoHS; Temperature: -40°C+85°C; Tolerance: NA; Voltage: NA; Wattage: NA; Weight: 311mg; Datasheet: Y:\MIS_DATABASE\DATASHEETS\MISC\CRY_OSC\ECS-2520MV.PDF
U72 = SN74LVC1G11DCKR_SC70-6: IC SINGLE 3-INPUT POSITIVE-AND GATE SON6; Chkd/date: MANIRAJA/270121; Crtd /date: ALVY/270121; Custom_Duty: 15%; Customs_HS_Code: 85423100; Distributor_name: DIGIKEY; Distributor_part_number: 296-30120-1-ND; Footprint Path: Y:\MIS_DATABASE\Library\ALTIUM_TOOL\PCB_FOOTPRINTS\Altium_Footprint_Lib.PcbLib; Height: 0.60MM; Library Path: Y:\MIS_DATABASE\Library\ALTIUM_TOOL\SCHEMATICS_PARTS\MS_GATE_Library.schlib; Mfr_name: TEXAS INSTRUMENTS; Mistral Part No: 141021010013-R; Package: SON6; Part_type: ICS\DIGITAL\GATES; Project: AM64X_SKEVM; RoHS: RoHS; Temperature: -40°C+125°C; Tolerance: NA; Voltage: NA; Wattage: NA; Weight: 33mg; Datasheet: Y:\MIS_DATABASE\DATASHEETS\ICS\DIGITAL\GATES\SN74LVC1G_NOV16.PDF
U90 = 74AHC1G08GW_SOT353-5: IC SINGLE 2-INPUT POSITIVE-AND GATE X2SON5; Chkd/date: MANIRAJA/141020; Crtd /date: ALVY/131020; Custom_Duty: 15%; Customs_HS_Code: 85423100; Distributor_name: DIGIKEY; Distributor_part_number: 296-40549-1-ND; Footprint Path: Y:\MIS_DATABASE\Library\ALTIUM_TOOL\PCB_FOOTPRINTS\Altium_Footprint_Lib.PcbLib; Height: 0.40MM; Library Path: Y:\MIS_DATABASE\Library\ALTIUM_TOOL\SCHEMATICS_PARTS\MS_GATE_Library.schlib; Manufacturer: TEXAS INSTRUMENTS; Mistral Part No: 141020100009-R; Package: X2SON5; Part_type: ICS\DIGITAL\GATES; Project: AM64X_SKEVM; RoHS: RoHS; Temperature: -40°C+125°C; Tolerance: NA; Voltage: NA; Wattage: NA; Weight: 0.6mg; Datasheet: Y:\MIS_DATABASE\DATASHEETS\ICS\DIGITAL\GATES\SN74LVC1G08XX.PDF
D12 D13 = DIODE_SOD323: DIODE 1CH ESD PROTECTION X1SON2; Chkd/date: MANIRAJA/040420; Crtd /date: VASANTHA/181114; Custom_Duty: 15%; Customs_HS_Code: 85423100; Distributor_name: DIGIKEY; Distributor_part_number: 296-30406-1-ND; Footprint Path: Y:\MIS_DATABASE\Library\ALTIUM_TOOL\PCB_FOOTPRINTS\Altium_Footprint_Lib.PcbLib; Height: 0.45MM; Library Path: Y:\MIS_DATABASE\Library\ALTIUM_TOOL\SCHEMATICS_PARTS\MS_DISCRETE_Library.schlib; Mfr_name: TEXAS INSTRUMENTS; Mistral Part No: 130014110022-R; Package: X1SON2; Part_type: DIODE; Project: GALILEO_EVM; RoHS: RoHS; Temperature: -40°C+125°C; Tolerance: NA; Voltage: NA; Wattage: NA; Weight: 1mg; Datasheet: Y:\MIS_DATABASE\DATASHEETS\ICS\INTERFACE\TPD1E10B06-SER.PDF
Q2 Q17 Q18 = MOSFET_IRLML6401TR: TRANSISTOR MOSFET P-CHANNEL SOT23-3; Chkd/date: SHREESHAIL/020206; Crtd /date: MAZHAR/040505; Custom_Duty: 15%; Customs_HS_Code: 85412900; Distributor_name: DIGIKEY; Distributor_part_number: IRLML6401PBFCT-ND; Height: 1.11MM; Mfr_name: IRF; Mfr_part_number: IRLML6401TRPBF; Mistral Part No: 130009031213-P; Package: SOT23-3; Part_type: TRANSISTOR\MOSFET; Project: G4_SVGA; RoHS: Pb-Free; Temperature: -55°C+150°C; Tolerance: NA; Voltage: NA; Wattage: NA; Weight: NA; Datasheet: Y:\MIS_DATABASE\DATASHEETS\DISCRETES\TRANSISTORS_FETS\IRLML6401.PDF
R550 = RESISTOR: RES 4.7K 1/20W 5% 0201; Chkd/date: MANIRAJA/200921; Crtd /date: ALVY/200921; Custom_Duty: 15%; Customs_HS_Code: 85332119; Distributor_name: DIGIKEY; Distributor_part_number: 311-4.7KNCT-ND; Footprint Path: Y:\MIS_DATABASE\Library\ALTIUM_TOOL\PCB_FOOTPRINTS\Altium_Footprint_Lib.PcbLib; Height: 0.26MM; Library Path: Y:\MIS_DATABASE\Library\ALTIUM_TOOL\SCHEMATICS_PARTS\MS_DISCRETE_Library.schlib; Manufacturer: YAGEO AMERICA; Mfr_name: YAGEO AMERICA; Mfr_part_number: RC0201JR-074K7L; Mistral Part No: 110021090007-R; Package: 0201; Part_type: RESISTORS\FIXED; Project: TI_AM62x SKEVM_BRD; RoHS: RoHS; Temperature: -55°C+125°C; Tolerance: 5%; Voltage: NA; Wattage: 1/20W; Weight: 0.17mg; Datasheet: Y:\MIS_DATABASE\DATASHEETS\RESISTORS\RCXXXXL-SER_MAR18.PDF
SW3 SW4 = 7914G-1-000E__7914G: SWITCH SPST-NO 4MM SQ SMD 7914G; Chkd/date: VASANTHA/271216; Crtd /date: BAVISH/051010; Custom_Duty: 24%; Customs_HS_Code: 85369090; Distributor_name: DIGIKEY; Distributor_part_number: 7914G-000ECT-ND; Height: 4.19MM; Library Ref: 7914G-1-000E _7914G; Mfr_name: BOURNS; Mistral Part No: 130015110004-R; Package: 7914G; Part_type: ELECTRO-MECHANICAL\SWITCH; Project: AAAUC; RoHS: RoHS; Temperature: -55°C+125°C; Tolerance: NA; Voltage: NA; Wattage: NA; Weight: NA; Datasheet: Y:\MIS_DATABASE\DATASHEETS\ICS\DIGITAL\COMBINATIONAL\7914G-1-000E.PDF
U82 = SN74LVC3G17DCUR_VSSOP8: IC TRIPLE SCHMITT-TRIGGER BUFFER VSSOP8; Chkd/date: MANIRAJA/280917; Crtd /date: MANIRAJA/280917; Custom_Duty: 15%; Customs_HS_Code: 85423100; Distributor_name: DIGIKEY; Distributor_part_number: 296-18818-1-ND; Height: 0.90MM; Mfr_name: TEXAS INSTRUMENTS; Mistral Part No: 141017090019-R; Package: VSSOP8; Part_type: ICS\DIGITAL\COMBINATIONAL; Project: TI_MAXIE_CPB; RoHS: RoHS; Temperature: -40°C+125°C; Tolerance: NA; Voltage: NA; Wattage: NA; Weight: 9.6mg; Datasheet: Y:\MIS_DATABASE\DATASHEETS\ICS\DIGITAL\COMBINATIONAL\SN74LVC3G17.PDF
ACC1 = ACCESSORY: STANDOFF BOARD TO BOARD 1.50MM LENGTH FEMALE M2 THREADED SS; Chkd/date: MANIRAJA/280219; Crtd /date: ALVY/280219; Distributor_name: DIGIKEY; Distributor_part_number: 732-7069-1-ND; Mfr_name: WURTH ELECTRONICS; Mistral Part No: 160019020049-R; Package: SS; Part_type: MECHANICAL\STANDOFF; Project: TI_J7ES_EVM_CP; RoHS: RoHS; Weight: 178mg; Datasheet: Y:\MIS_DATABASE\DATASHEETS\MISC\MECHANICAL\9774015243R.PDF
FID1-FID6 = Fiducial
LBL1-LBL3 = ACCESSORY_THT-3-423-10: ACCESSORIE 1 WORKHORSE POLYSTER LABLE 0.25" X 1"; Chkd/date: MANIRAJA/270218; Crtd /date: ALVY/260218; Footprint Path: Y:\MIS_DATABASE\Library\ALTIUM_TOOL\PCB_FOOTPRINTS\Altium_Footprint_Lib.PcbLib; Library Path: Y:\MIS_DATABASE\Library\ALTIUM_TOOL\SCHEMATICS_PARTS\MS_MECHANICAL_Library.schlib; Mfr_name: BRADY; Mistral Part No: 160018020185; Part_type: ACCESSORIES; Project: TI_MAXIE_CPB
LOGO1 LOGO3 LOGO4 = TI_Logo
LOGO2 = FCC_disclaimer
MH1 = WASHER_FLAT: FLAT WASHER FOR M2 NYLON; Chkd/date: MANIRAJA/110319; Crtd /date: ALVY/110319; Distributor_name: DIGIKEY; Distributor_part_number: 36-3356-ND; Mfr_name: KEYSTONE; Mfr_part_number: 3356; Mistral Part No: 160019030017-R; Package: NYLON; Part_type: MECHANICAL\WASHERS; Project: TI_J7ES_EVM_CP; RoHS: RoHS; Datasheet: Y:\MIS_DATABASE\DATASHEETS\MISC\MECHANICAL\3356.PDF
MH2 = SCREW_PAN: PHILLIPS PAN HEAD SCREW - M2 X 5; Chkd/date: MANIRAJA/150319; Crtd /date: MANIRAJA/150319; Distributor_name: DIGIKEY; Distributor_part_number: H738-ND; Height: 5.00MM; Mfr_name: B AND F FASTENER; Mfr_part_number: MPMS 002 0005 PH; Mistral Part No: 160019030026-R; Part_type: MECHANICAL\SCREWS; Project: TI_J7ES_EVM_CP; RoHS: RoHS; Datasheet: Y:\MIS_DATABASE\DATASHEETS\MISC\MECHANICAL\SCREW_MPMSXXX.PDF
PCB1 = PCB: AM62x SKEVM Bare PCB

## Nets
DGND: C156.1 C334.1 C429.1 C446.1 C469.1 C470.1 C472.1 C491.1 C541.2 C542.1 D12.1 D13.1 Q2.3(D) Q17.3(D) Q18.3(D) R201.2 R381.2 R472.2 SW3.1 SW3.4 SW4.1 SW4.4 U53.2(GND) U72.2(GND) U82.4(GND) U90.3(GND) ; also on sheet 1 3 12 13 14 15 16 17 18 19 20 21 22 23 24 25 26 27 28 29 30 31 32 33 34 35 36 37 38 39 40 41 42 43
VCC1V8_CLKBUF: C334.2 C541.1 R370.1 U53.4(VDD) ; also on sheet 27
VCC_1V8: C429.2 R220.1 U72.5(VCC) ; also on sheet 14 15 20 21 23 27 36 39 41 42
VCC_3V3_SYS: C446.2 C472.2 R200.1 R391.1 R392.1 R490.1 R491.1 R538.1 R572.2 R575.1 R576.1 R584.1 R681.1 U82.8(VCC) U90.5(VCC) ; also on sheet 3 12 14 15 16 20 21 22 24 25 26 27 28 29 31 32 33 34 35 36 37 38 39 40 41 42 43
CLKOUT0: R384.2 R385.2 ; also on sheet 27
CLKOUT_OSC: R384.1 U53.3(OUTPUT)
CONN_MCU_PORz: U72.1(A) ; also on sheet 36
CONN_MCU_RESETz: Q2.1(G) ; also on sheet 36
CPSW_RGMII_INTn/PRU_INTn: R613.1 ; also on sheet 25 34
DEBOUNCE_GPIO_INT_SoC: C469.2 D12.2 Q17.2(S) R575.2 SW4.2 SW4.3 U82.3(2A)
Debounce_MCU_RESETz: C156.2 Q2.2(S) R200.2 TP68.1(TP) U82.1(1A)
DEBOUNCE_SOC_WARMRESETn: C470.2 D13.2 Q18.2(S) R576.2 SW3.2 SW3.3 U82.6(3A)
EXP_CLKOUT0: R336.1 ; also on sheet 35
EXP_GPIO1_22: U12.A15(UART0_CTSN) ; also on sheet 35
EXP_SPI0_CLK: R761.2 ; also on sheet 35
EXP_SPI0_CS0: U12.A13(SPI0_CS0) ; also on sheet 35
EXP_SPI0_CS1: U12.C13(SPI0_CS1) ; also on sheet 35
EXP_SPI0_D0: U12.B13(SPI0_D0) ; also on sheet 35
EXP_SPI0_D1: U12.B14(SPI0_D1) ; also on sheet 35
EXP_UART5_RXD: U12.C15(MCAN0_TX) ; also on sheet 35
EXP_UART5_TXD: U12.E15(MCAN0_RX) ; also on sheet 35
EXT_CLKOUT0: R337.2 R385.1
EXT_CLKOUT0_R: R336.2 R337.1 U12.A18(EXT_REFCLK1)
EXTINTn_RC: C491.2 R613.2 R681.2 TP25.1(TP) U12.D16(EXTINTN) ; also on sheet 15
GPIO1_23_INTn: R550.2 U12.B15(UART0_RTSN) ; also on sheet 41
GPIO_SoC: R550.1 U82.5(2Y)
JTAG_EMU_RSTn: U90.1(B) ; also on sheet 32
MCU_PORz: C542.2 R201.1 R220.2 TP69.1(TP) U12.D2(MCU_PORZ) U72.4(Y)
MCU_RESETSTATz: U12.B12(MCU_RESETSTATZ) ; also on sheet 34 36
MCU_RESETz: R538.2 TP78.1(TP) U12.E11(MCU_RESETZ) U82.7(1Y)
MCU_SAFETY_ERRORz_1V8: U12.D1(MCU_ERRORN) ; also on sheet 36
PMIC_PGOOD: U90.2(A) ; also on sheet 15 37
PORz_OUT: R381.1 TP34.1(TP) U12.E21(PORZ_OUT) ; also on sheet 22 25 26 29
RESETSTATz: R472.1 TP64.1(TP) U12.F22(RESETSTATZ) ; also on sheet 15 21 22 23 25 26 29 34 35 39 41 42 43
SoC_I2C0_SCL: R391.2 R757.2 ; also on sheet 12 15 24 34 35 39
SoC_I2C0_SDA: R392.2 R758.2 ; also on sheet 12 15 24 34 35 39
SOC_I2C1_SCL: R491.2 R759.2 ; also on sheet 3 16 24 28 41 42 43
SOC_I2C1_SDA: R490.2 R760.2 ; also on sheet 3 16 24 28 41 42 43
SoC_PORz: R584.2 U72.3(B) U90.4(Y)
SOC_UART0_RX_3V3: U12.D14(UART0_RXD) ; also on sheet 33
SOC_UART0_TX_3V3: U12.E14(UART0_TXD) ; also on sheet 33
SoC_WARM_RESETZ: R572.1 TP85.1(TP) U12.F20(RESET_REQZ) U82.2(3Y)
TEST_GPIO1: Q17.1(G) ; also on sheet 3 28
TEST_PORZn: U72.6(C) ; also on sheet 3 28
TEST_WARMRESETn: Q18.1(G) ; also on sheet 3 28
N16947096: R370.2 U53.1(TRI-STATE)
N22130443: R757.1 U12.B16(I2C0_SCL)
N22130446: R758.1 U12.A16(I2C0_SDA)
N22130449: R759.1 U12.B17(I2C1_SCL)
N22130452: R760.1 U12.A17(I2C1_SDA)
N22130779: R761.1 U12.A14(SPI0_CLK)

Not connected (* = marked no-connect by the designer): U12 A2(RSVD1)* AE2(RSVD3)* B1(RSVD0)* F6(RSVD2)*

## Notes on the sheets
sheet 44
- D-Note:
  Open-drain output type buffer
  I2C interfaces have slew rate
  requirement specified when
  pulled to 3.3 V. An RC can be
  used to limit the slew rate
- D-Note:
  I2C0_, I2C1_
  Emulated Open Drain output type
  I2C interface. 47R series resistor
  is added to control the fall time
  Note the exceptions related to
  emulated open drain output type
  I2C interface in the data sheet
- OSCILLATOR
- SOC - GENERAL
- GPIO1_22
- D-Note:
  Add 10K pulldown
  when EXT_CLKOUT0
  is configured as
  peripheral clock
- GPIO1_23
- C
- D-Note:
  SoC IO buffers are off during reset.
  A pull is recommended near to the
  attached device that is being driven
  by the SoC IO.
- D-Note:
  EXT_REFCLK1 is used as CLKOUT0.
  A clock signal should always be
  connected point-to-point without
  any branches. When connecting
  CLKOUT to more than one
  (multiple) clock inputs, use a
  buffer with one input and
  multiple outputs.
- D-Note:
  RESERVED PINS
  Leave them
  unconnected
- D-Note:
  RESERVED PINS
  Leave them unconnected
- D-Note:
  Recommended
  oscillator
  part number
  LMK6CE02500DDLFT
- ECS-2520MV-250-CN-TR
- D-Note:
  Refer to the SoC data sheet for oscillator
  specifications when the oscillator is used
  along with clock buffer and also when
  the oscillator is directly connected as
  SoC clock input.
- D-Note:
  Provide provision for a pull-down. Populate when an
  attached device is connected. Refer to the SoC datasheet
  for Pin Connectivity Requirements.
- SOC - RESETS
- D-Note:
  EXTINTn is an open-drain output type buffer, fail-safe IO. An external
  pull-up is recommended when a trace or external input is connected.
- V.
- D-Note:
  Pull-down resistor on PORz_OUT and RESETSTATz is provided to hold the
  attached device in reset condition during SoC reset and power-up.
- D-Note:
  Open-drain output type IO EXTINTn has slew rate limit specified,
  when pulled to a 3.3 V supply. An RC is added to limit the slew rate
- V.
- MCU POWER ON RESET
- D-Note:
  MCU_PORz inputs have slew rate
  requirements specified. Lesser the
  slew, the better when PMIC_POWERGOOD
  is connected as MCU_PORz input. Adjust
  the PMIC_POWERGOOD pull-up to
  minimize the slew (100-200
  ns) when using an open drain
  output. MCU_PORz is fail-safe and
  3.3 V tolerant. Therefore, you can
  pull the MCU_PORz signal to either
  1.8 V or 3.3 V.
- R-Note:
  MCU_PORz has pull-down configured.
- D-Note:
  Not connecting a valid MCU_PORz could cause
  unpredictable and probably random behavior. Since
  the device is not getting a valid reset, internal
  circuits would be in random states. Slow rising
  reset signal could cause glitches internal to the
  SoC reset circuit. The recommendation is to
  connect the output from the logic gate or a
  discrete buffer (with fast rise time)
  as input to MCU_PORz, rather than a slow rising
  open-drain output (from PMIC of similar sources).
- D-Note:
  22pF glitch filter
  has been added
  to improve EMC
  robustness
- C
sheet 45
- EXTERNAL RESET INPUT AND SCHMITT TRIGGER DEBOUNCE LOGIC
- DEBOUNCE CIRCUIT
- D-Note:
  LVCMOS inputs have slew rate requirements specified. A
  Schmitt trigger based debouncing logic is used  for the
  slow ramp warm reset inputs. Debounce circuit is
  recommended  when push button or RC is used.
- MCU WARM RESET
- D-Note:
  Add a 22pF glitch filter
  near to the processor
  WARM reset inputs
- D-Note:
  DNI Q2 and C156.
  Refer to errata:
  i2407— RESET: MCU_RESETSTATz unreliable when MCU_RESETz is asserted low.
- SOC WARM RESET
- Silk: RST
- USER INTERRUPT
- Silk: INT
sheet 46
- MOUNTING HARDWARE
- LOGOs
- ASSEMBLY NOTES
- BARE PCB
- 1. All MSL components should be baked as per JEDEC standard.
  2. PCB should be baked at 120 degree for 8 hours.
  3. Board assembly must comply with workmanship standards.
  IPC-A-610 Class 2, unless otherwise specified.
  4. These assemblies are ESD sensitive, ESD precautions
  shall be observed.
  5. These assemblies must be clean and free from flux and
  all contaminants. Use of no clean flux is not acceptable.
  6. Provide serial numbers to the assembled boards for identification.
  7. The assembled board are wrapped in ESD Covers(individual) and
  packed securely before shipment.
- Texas Intruments
- For Evaluation only; not FCC approved for resale
- WEEE Mark
- CE Mark
- STANDOFF,SCREW & WASHER FOR PCIe M.2
- LABELS
- Board Serial No.
- Assembly Revision
- 3356
- MPMS 002 0005 PH
- FIDUCIALS
- ORDERABLE PART NO
- R-Note:
  Refer to STRAP CONFIGURATION OF ETHERNET PHYS
  page from SK-AM64B schematics.
- Oderable Part Number
- Variant
- Label Text
- 001
- SK-AM62-P1
- 002
- SK-AM62B-P1
